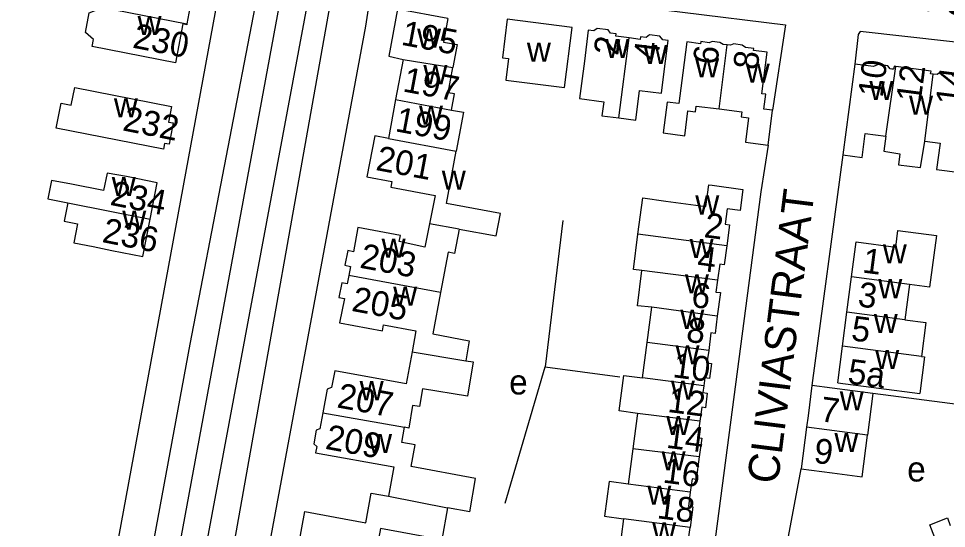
# Model space of a CAD drawing. Extents: x 161258 to 163262, y 380749 to 382054.
# Drawn here: x 161736.2 to 161885.6, y 381231.9 to 381313.9 of the extents above; entities that cross this region are included whole.
import ezdxf

# ---------------------------------------------------------------- set-up
doc = ezdxf.new("R2010")
doc.units = 0
for name, color, linetype in [('BLT_Basislijn', 7, 'Continuous'), ('BLT_Bebouwing', 7, 'Continuous'), ('BLT_Centroide', 7, 'Continuous'), ('BLT_Huisnummer', 7, 'Continuous'), ('BLT_Huisnummer_ tussenligend', 7, 'Continuous'), ('BLT_Onderverdeling_panden', 7, 'Continuous'), ('BLT_Straatnaam', 7, 'Continuous')]:
    doc.layers.add(name, color=color, linetype=linetype)

msp = doc.modelspace()

# ---------------------------------------------------------------- linework, layer by layer
at = {"layer": 'BLT_Basislijn'}
for p, q in [((161738.24, 381154.1), (161769.73, 381324.83)), ((161786.63, 381317.86), (161762.57, 381182.82)), ((161856.88, 381293.56), (161855.69, 381286.08)), ((161868.93, 381292.01), (161863.94, 381254.87)), ((161823.84, 381281.43), (161820.96, 381257.91)), ((161814.56, 381235.95), (161820.96, 381257.91)), ((161820.96, 381257.91), (161832.98, 381256.29)), ((161892.14, 381251.23), (161873.75, 381253.6))]:
    msp.add_line(p, q, dxfattribs=at)
for points in [[(161779.51, 381323.45), (161738.07, 381099.04), (161732.89, 381072.3)], [(161783.84, 381322.64), (161743.98, 381109.19), (161741.35, 381090.28)], [(161793.34, 381321.17), (161792.04, 381312.74), (161767.53, 381180.66)], [(161793.34, 381321.17), (161859.66, 381312.96), (161857.6, 381299.2)], [(161774.85, 381318.89), (161763.77, 381261.52), (161730.62, 381082.27)], [(161917.28, 381306.42), (161900, 381308.69), (161871.68, 381311.89), (161871.35, 381311.38), (161870.84, 381306.62)], [(161855.69, 381286.08), (161847.79, 381226.12), (161851.56, 381216.5)], [(161861.39, 381224.15), (161859.97, 381227.91), (161859.85, 381228.88), (161862.21, 381241.48)]]:
    msp.add_lwpolyline(points, dxfattribs=at)
at = {"layer": 'BLT_Bebouwing'}
for p, q in [((161762.64, 381313.08), (161761.47, 381306.8)), ((161761.47, 381306.8), (161748.04, 381309.44)), ((161798.12, 381307.35), (161796.91, 381300.9)), ((161870.84, 381306.62), (161868.93, 381292.01)), ((161745.24, 381302.86), (161760.81, 381299.8)), ((161796.91, 381300.9), (161795.75, 381294.67)), ((161742.28, 381296.3), (161743.07, 381300.33)), ((161760.81, 381299.8), (161760.34, 381297.29)), ((161856.88, 381293.56), (161857.6, 381299.2)), ((161759.52, 381292.92), (161742.28, 381296.3)), ((161760.34, 381297.29), (161761.08, 381297.15)), ((161761.08, 381297.15), (161760.43, 381293.71)), ((161759.7, 381293.85), (161759.52, 381292.92)), ((161760.43, 381293.71), (161759.7, 381293.85)), ((161744.12, 381284.28), (161743.54, 381281.32)), ((161756.22, 381275.68), (161757.38, 381281.68)), ((161748.21, 381277.25), (161751.23, 381276.64)), ((161751.23, 381276.64), (161756.22, 381275.68)), ((161869.57, 381266.69), (161870.31, 381272.37)), ((161879.64, 381271.16), (161878.9, 381265.47)), ((161837.39, 381261.81), (161838.15, 381267.51)), ((161868.86, 381261.21), (161869.57, 381266.69)), ((161836.63, 381256.1), (161837.39, 381261.81)), ((161868.1, 381255.33), (161868.86, 381261.21)), ((161873.75, 381253.6), (161863.94, 381254.87)), ((161868.1, 381255.33), (161881.28, 381253.62)), ((161873.75, 381253.6), (161872.88, 381246.91)), ((161863.08, 381248.18), (161862.21, 381241.48)), ((161835.11, 381244.71), (161834.34, 381239.01)), ((161808.83, 381234.58), (161805.28, 381235.22))]:
    msp.add_line(p, q, dxfattribs=at)
for points in [[(161749.27, 381315.82), (161749.31, 381316.02), (161750.34, 381321.4), (161753.55, 381320.79), (161753.57, 381320.93), (161754.41, 381320.77), (161754.55, 381321.51), (161758.58, 381320.71), (161758.44, 381319.98), (161759.26, 381319.81), (161759.33, 381320.16), (161764.42, 381319.16), (161763.3, 381313.08)], [(161748.04, 381309.44), (161748.26, 381310.57), (161746.98, 381311.7), (161747.59, 381314.89), (161749.21, 381315.51), (161749.27, 381315.82)], [(161805.32, 381313.94), (161797.23, 381315.45), (161795.82, 381307.91), (161798.12, 381307.35)], [(161763.3, 381313.08), (161763.27, 381312.96), (161762.64, 381313.08)], [(161805.32, 381313.94), (161804.62, 381310.17), (161806.83, 381309.75), (161806.14, 381306.05)], [(161834.49, 381310.82), (161832.38, 381311.09), (161832.43, 381311.49), (161831.52, 381311.61), (161831.13, 381312.12), (161829.33, 381312.35), (161828.82, 381311.95), (161827.92, 381312.07), (161827.29, 381307.11), (161826.83, 381303.47), (161826.52, 381301.07), (161830.41, 381300.57), (161830.12, 381298.3), (161832.85, 381297.95)], [(161832.85, 381297.95), (161835.57, 381297.6), (161836.18, 381302.37), (161839.7, 381301.92), (161840.15, 381305.44), (161840.78, 381310.4), (161839.92, 381310.51), (161839.47, 381311.09), (161837.76, 381311.31), (161837.22, 381310.89), (161836.31, 381311), (161836.26, 381310.6), (161834.49, 381310.82)], [(161850.28, 381309.7), (161849.65, 381309.78), (161849.12, 381310.1), (161847.87, 381310.26), (161847.39, 381310.05), (161846.02, 381310.23), (161845.98, 381309.9), (161843.77, 381310.18), (161843.14, 381305.22), (161842.5, 381300.27), (161840.61, 381300.51), (161839.98, 381295.54), (161843.46, 381295.1), (161843.97, 381299.12), (161845.18, 381298.96), (161845.29, 381299.86), (161848.97, 381299.4)], [(161857.6, 381299.2), (161856.21, 381299.37), (161856.51, 381301.76), (161855.89, 381301.84), (161856.74, 381308.53), (161854.51, 381308.81), (161854.55, 381309.13), (161853.21, 381309.3), (161852.69, 381309.69), (161851.34, 381309.86), (161850.81, 381309.64), (161850.28, 381309.7)], [(161876.8, 381305.82), (161876.54, 381305.85), (161876.17, 381306.34), (161874.6, 381306.55), (161873.83, 381306.23), (161870.84, 381306.62)], [(161805.88, 381299.23), (161806.37, 381301.84), (161805.38, 381302.02), (161806.14, 381306.05)], [(161877.42, 381306.23), (161877.15, 381306.27), (161877.08, 381305.78), (161876.8, 381305.82)], [(161883.43, 381305.01), (161883.04, 381305.06), (161883.1, 381305.49), (161877.42, 381306.23)], [(161889.79, 381304.25), (161886.7, 381304.66), (161886.33, 381305.14), (161884.66, 381305.36), (161884.09, 381304.93), (161883.43, 381305.01)], [(161743.07, 381300.33), (161744.68, 381300.01), (161745.24, 381302.86)], [(161805.88, 381299.23), (161807.84, 381298.86), (161806.67, 381292.63)], [(161848.97, 381299.4), (161852.65, 381298.93), (161852.54, 381298.11), (161853.71, 381297.96), (161853.21, 381294.03), (161856.88, 381293.56)], [(161795.75, 381294.67), (161793.54, 381295.08), (161792.3, 381288.45), (161796.32, 381287.7), (161796.15, 381286.81), (161803.26, 381285.45), (161802.37, 381280.93)], [(161868.93, 381292.01), (161872.02, 381291.6), (161872.51, 381295.43), (161875.84, 381295.02)], [(161875.84, 381295.02), (161875.48, 381292.59), (161878.1, 381292.2), (161877.87, 381290.42), (161881.43, 381289.96), (161882.08, 381294.22)], [(161882.08, 381294.22), (161884.56, 381293.9), (161884.01, 381289.67), (161887.82, 381289.17)], [(161805.09, 381284.17), (161806.67, 381292.63)], [(161757.38, 381281.68), (161758.51, 381287.52), (161753.56, 381288.53), (161750.45, 381289.07), (161749.9, 381286.26), (161744.71, 381287.28), (161741.52, 381287.9), (161740.91, 381284.93), (161744.12, 381284.28)], [(161835.92, 381279.25), (161836.68, 381285.12), (161840.43, 381284.56), (161846.85, 381283.7), (161847.31, 381287.2), (161847.85, 381287.12), (161852.81, 381286.46), (161852.35, 381283.04), (161850.27, 381283.32), (161849.95, 381280.85), (161850.67, 381280.75), (161850.22, 381277.39)], [(161807.14, 381280.05), (161813.08, 381278.96), (161813.8, 381282.58), (161805.09, 381284.17)], [(161743.54, 381281.32), (161745.7, 381280.9), (161745.1, 381277.86), (161748.21, 381277.25)], [(161802.37, 381280.93), (161801.63, 381277.15), (161797.5, 381278.09), (161797.68, 381279.04), (161790.81, 381280.33), (161790.12, 381276.43), (161789.2, 381276.61), (161788.75, 381274.24), (161789.67, 381274.07), (161789.39, 381272.59)], [(161807.14, 381280.05), (161806.38, 381276.16), (161805.35, 381276.37), (161804.13, 381269.84)], [(161870.31, 381272.37), (161871.04, 381277.99), (161877.43, 381277.16), (161877.78, 381279.84), (161883.96, 381279.03), (161882.88, 381270.74), (161879.64, 381271.16)], [(161836.57, 381273.4), (161835.18, 381273.58), (161835.92, 381279.25)], [(161850.22, 381277.39), (161849.81, 381274.32), (161849.08, 381274.42), (161848.73, 381271.82)], [(161789.39, 381272.59), (161789.13, 381271.24), (161788.24, 381271.41), (161787.78, 381269.05), (161788.68, 381268.88), (161787.9, 381264.98), (161794.79, 381263.68), (161794.98, 381264.66), (161800.18, 381263.69), (161799.55, 381260.29)], [(161838.15, 381267.51), (161835.86, 381267.73), (161836.57, 381273.4)], [(161848.73, 381271.82), (161848.48, 381269.94), (161849.21, 381269.84), (161848.7, 381266.06)], [(161804.13, 381269.84), (161802.89, 381263.19), (161808.74, 381262.09), (161808.22, 381258.88)], [(161848.7, 381266.06), (161848.33, 381263.26), (161847.65, 381263.35), (161847.31, 381260.52)], [(161878.9, 381265.47), (161882.29, 381265.04), (161881.58, 381259.55)], [(161799.55, 381260.29), (161798.6, 381255.14), (161787.11, 381257.26), (161786.6, 381254.55), (161785.87, 381254.29), (161785.17, 381250.5)], [(161847.31, 381260.52), (161847.01, 381258.55), (161847.74, 381258.45), (161847.42, 381256.02), (161846.7, 381256.12), (161846.52, 381254.82)], [(161808.22, 381258.88), (161809.4, 381258.69), (161808.5, 381253.17), (161801.22, 381254.35), (161800.76, 381251.5), (161799.64, 381251.68), (161799.06, 381248.05), (161798.35, 381248.17)], [(161881.58, 381259.55), (161882.05, 381259.49), (161881.28, 381253.62)], [(161835.87, 381250.41), (161832.92, 381250.82), (161833.66, 381256.49), (161836.63, 381256.1)], [(161846.52, 381254.82), (161846.38, 381253.75), (161847.09, 381253.65), (161846.78, 381251.32), (161846.18, 381251.4), (161845.88, 381249.14)], [(161863.94, 381254.87), (161863.31, 381250), (161863.08, 381248.18)], [(161785.17, 381250.5), (161784.69, 381247.92), (161784.13, 381247.72), (161783.72, 381245.5), (161784.22, 381245.07), (161784.02, 381244.04)], [(161835.87, 381250.41), (161835.81, 381250), (161835.11, 381244.71)], [(161845.88, 381249.14), (161845.53, 381246.51), (161846.19, 381246.42), (161845.79, 381243.39)], [(161808.83, 381234.58), (161809.79, 381239.95), (161799.39, 381241.85), (161800.03, 381245.32), (161797.92, 381245.71), (161798.35, 381248.17)], [(161862.21, 381241.48), (161867.17, 381240.84), (161872.02, 381240.21), (161872.88, 381246.91)], [(161784.02, 381244.04), (161796.64, 381241.8), (161795.76, 381237.07)], [(161845.79, 381243.39), (161845.3, 381239.76), (161844.65, 381239.85), (161844.34, 381237.71)], [(161834.34, 381239.01), (161831.27, 381239.42), (161830.52, 381233.86), (161833.6, 381233.44)], [(161792.1, 381232.81), (161792.97, 381237.58), (161795.76, 381237.07)], [(161844.34, 381237.71), (161844.05, 381235.43), (161844.75, 381235.34), (161844.31, 381232.05)], [(161805.28, 381235.22), (161804.34, 381230.07), (161794.47, 381231.88), (161793.52, 381226.66), (161794.3, 381226.51), (161793.14, 381220.18), (161790.9, 381220.59), (161790.82, 381220.17), (161789.83, 381220.35), (161784.91, 381221.25), (161785.37, 381223.75), (161780.43, 381224.65), (161780.62, 381225.68), (161779.82, 381226.36), (161780.19, 381228.42), (161781.21, 381228.79), (161782.28, 381234.61), (161787.2, 381233.71), (161792.1, 381232.81)], [(161833.6, 381233.44), (161832.82, 381227.65), (161837.9, 381226.97), (161842.85, 381226.3), (161843.19, 381228.79), (161843.86, 381228.7), (161844.31, 381232.05)], [(161882.05, 381226.55), (161884.78, 381227.61), (161882.89, 381232.48), (161885.73, 381233.57), (161886.2, 381232.36)]]:
    msp.add_lwpolyline(points, dxfattribs=at)
msp.add_lwpolyline([(161814.88, 381313.84), (161814.09, 381307.64), (161815.08, 381307.51), (161814.64, 381304.05), (161824.1, 381302.85), (161825.33, 381312.5)], close=True, dxfattribs=at)
at = {"layer": 'BLT_Onderverdeling_panden'}
for p, q in [((161749.27, 381315.82), (161763.3, 381313.08)), ((161832.85, 381297.95), (161834.49, 381310.82)), ((161848.97, 381299.4), (161850.28, 381309.7)), ((161798.12, 381307.35), (161806.14, 381306.05)), ((161875.84, 381295.02), (161877.42, 381306.23)), ((161882.08, 381294.22), (161883.43, 381305.01)), ((161796.91, 381300.9), (161805.88, 381299.23)), ((161795.75, 381294.67), (161806.67, 381292.63)), ((161744.12, 381284.28), (161757.38, 381281.68)), ((161807.14, 381280.05), (161802.37, 381280.93)), ((161850.22, 381277.39), (161835.92, 381279.25)), ((161804.13, 381269.84), (161789.39, 381272.59)), ((161848.73, 381271.82), (161836.57, 381273.4)), ((161879.64, 381271.16), (161870.31, 381272.37)), ((161848.7, 381266.06), (161838.15, 381267.51)), ((161878.9, 381265.47), (161869.57, 381266.69)), ((161847.31, 381260.52), (161837.39, 381261.81)), ((161799.55, 381260.29), (161808.22, 381258.88)), ((161881.58, 381259.55), (161868.86, 381261.21)), ((161846.52, 381254.82), (161836.63, 381256.1)), ((161785.17, 381250.5), (161798.35, 381248.17)), ((161845.88, 381249.14), (161835.87, 381250.41)), ((161872.88, 381246.91), (161863.08, 381248.18)), ((161845.79, 381243.39), (161835.11, 381244.71)), ((161844.34, 381237.71), (161834.34, 381239.01)), ((161795.76, 381237.07), (161805.28, 381235.22)), ((161844.31, 381232.05), (161833.6, 381233.44))]:
    msp.add_line(p, q, dxfattribs=at)

# ---------------------------------------------------------------- texts
at = {"layer": 'BLT_Centroide'}
for s, p in [('w', (161755.36, 381311.31)), ('w', (161800.37, 381309.25)), ('w', (161818.04, 381306.99)), ('w', (161830.66, 381307.58)), ('w', (161836.81, 381306.61)), ('w', (161845.12, 381304.48)), ('w', (161853.28, 381303.64)), ('w', (161801.38, 381303.38)), ('w', (161873.17, 381300.83)), ('w', (161751.55, 381298.06)), ('w', (161879.56, 381298.47)), ('w', (161800.67, 381296.88)), ('w', (161804.34, 381286.41)), ('w', (161751.21, 381285.38)), ('w', (161845.15, 381282.41)), ('w', (161752.9, 381279.97)), ('w', (161794.65, 381275.44)), ('w', (161844.23, 381275.41)), ('w', (161875.34, 381274.56)), ('w', (161843.48, 381269.72)), ('w', (161796.52, 381267.72)), ('w', (161874.6, 381268.94)), ('w', (161842.73, 381264)), ('w', (161873.88, 381263.34)), ('w', (161841.97, 381258.28)), ('w', (161874.11, 381257.53)), ('e', (161815.19, 381253.45)), ('w', (161791.12, 381252.53)), ('w', (161841.22, 381252.62)), ('w', (161868.41, 381250.88)), ('w', (161840.48, 381246.91)), ('w', (161792.47, 381244.02)), ('w', (161867.55, 381244.19)), ('w', (161839.72, 381241.22)), ('e', (161879.27, 381239.44)), ('w', (161837.43, 381235.72)), ('w', (161838.21, 381229.81))]:
    msp.add_text(s, height=4, dxfattribs=at).set_placement(p)
at = {"layer": 'BLT_Huisnummer'}
for s, rotation, p in [('230', 348.9259, (161754.42, 381309.29)), ('195', 349.4115, (161797.66, 381309.75)), ('2', 82.7371, (161832.73, 381307.9)), ('8', 82.7336, (161855.18, 381305.57)), ('10', 82.5476, (161875.29, 381301.13)), ('14', 82.9129, (161887.79, 381299.84)), ('232', 348.9, (161752.81, 381295.97)), ('201', 349.4087, (161793.58, 381289.59)), ('234', 348.9201, (161750.79, 381283.98)), ('236', 348.9283, (161749.51, 381277.99)), ('2', 352.5847, (161846.43, 381278.77)), ('203', 349.4313, (161791, 381273.87)), ('1', 352.6211, (161871.93, 381273.09)), ('6', 352.5817, (161844.37, 381267.56)), ('205', 349.4092, (161789.68, 381266.92)), ('5', 352.6274, (161870.12, 381262.18)), ('10', 352.5834, (161841.39, 381256.25)), ('5a', 352.631, (161869.55, 381255.24)), ('207', 349.6068, (161787.32, 381251.39)), ('7', 352.6206, (161865.12, 381249.16)), ('209', 349.6091, (161785.44, 381244.72)), ('14', 352.5811, (161840.36, 381244.89)), ('9', 352.6292, (161864.1, 381242.48))]:
    msp.add_text(s, height=4, rotation=rotation, dxfattribs=at).set_placement(p)
at = {"layer": 'BLT_Huisnummer_ tussenligend'}
for s, rotation, p in [('4', 82.7371, (161839.14, 381307.07)), ('6', 82.7371, (161848.69, 381306.39)), ('197', 349.4115, (161797.92, 381302.24)), ('12', 82.5476, (161881.43, 381300.33)), ('199', 349.4115, (161796.7, 381295.83)), ('4', 352.5847, (161845.32, 381273.45)), ('3', 352.6303, (161871.19, 381267.64)), ('8', 352.5817, (161843.56, 381261.96)), ('12', 352.5834, (161840.58, 381250.65)), ('16', 352.5811, (161839.81, 381239.29)), ('18', 352.5811, (161838.87, 381233.55))]:
    msp.add_text(s, height=4, rotation=rotation, dxfattribs=at).set_placement(p)
at = {"layer": 'BLT_Straatnaam'}
for s, rotation, p in [('ST GERARDUSLAAN', 352.6663, (161846.19, 381319.8)), ('CLIVIASTRAAT', 82.8529, (161858.45, 381238.91))]:
    msp.add_text(s, height=5, rotation=rotation, dxfattribs=at).set_placement(p)

doc.saveas('drawing.dxf')
